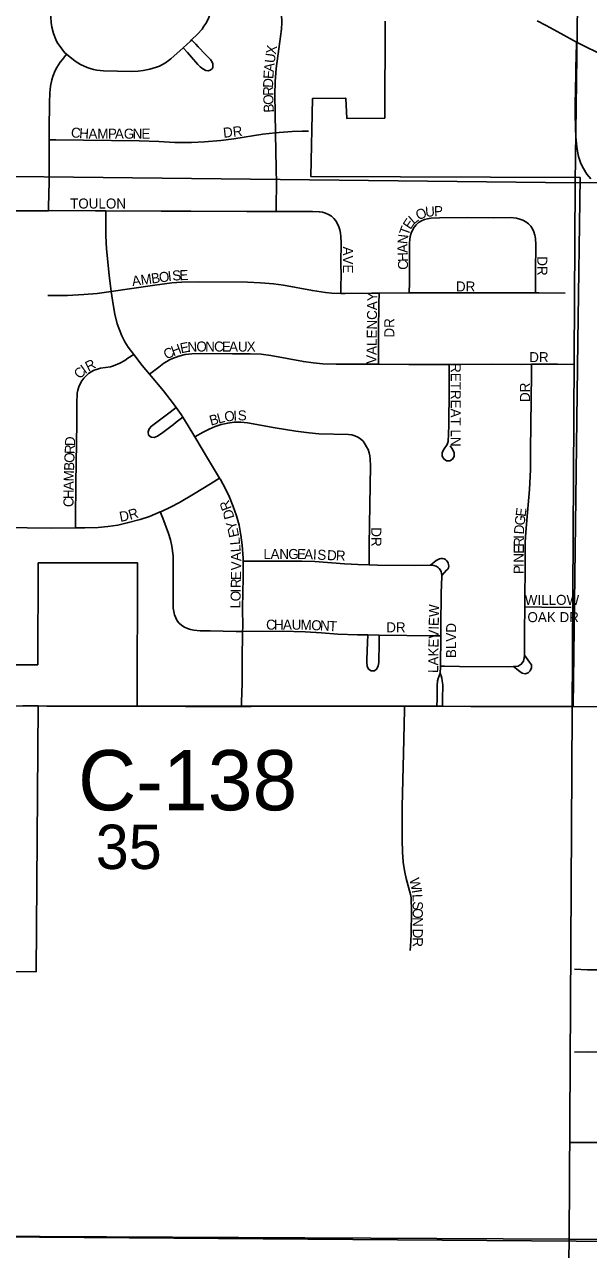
# Model space of a CAD drawing. Extents: x -97 to 34, y -21 to 22.
# Drawn here: x 7.079 to 7.611, y 17.448 to 18.604 of the extents above; entities that cross this region are included whole.
import ezdxf

# ---------------------------------------------------------------- set-up
doc = ezdxf.new("R2010")
doc.units = 0
for name, color, linetype in [('GM_X_City_Street', 7, 'Continuous'), ('GM_X_City_Street_Text', 7, 'Continuous'), ('GM_X_Corporation', 7, 'Continuous'), ('GM_X_County_Road', 7, 'Continuous'), ('GM_X_County_Road_Text', 7, 'Continuous'), ('GM_X_Section', 7, 'Continuous'), ('GM_X_Section_Text', 7, 'Continuous'), ('GM_X_State_Route', 7, 'Continuous'), ('GM_X_Township', 7, 'Continuous'), ('GM_X_Township_Subdivision', 7, 'Continuous'), ('GM_X_Township_Subdivision_Text', 7, 'Continuous')]:
    doc.layers.add(name, color=color, linetype=linetype)

msp = doc.modelspace()

# ---------------------------------------------------------------- linework, layer by layer
at = {"layer": 'GM_X_City_Street'}
for points in [[(7.3157, 18.5021), (7.315, 18.5384), (7.3153, 18.5507), (7.3163, 18.563), (7.3187, 18.5815), (7.3208, 18.5954), (7.3211, 18.5978), (7.3213, 18.5999), (7.3215, 18.6062), (7.321, 18.6217), (7.3209, 18.6341), (7.3203, 18.6589), (7.3198, 18.6775), (7.3192, 18.6838), (7.3186, 18.6869), (7.3178, 18.69), (7.3169, 18.6923)], [(7.2364, 18.5898), (7.2421, 18.5953), (7.2463, 18.6001), (7.2481, 18.6027), (7.2498, 18.6054), (7.2514, 18.6082), (7.2527, 18.611), (7.2549, 18.617), (7.2557, 18.6201), (7.2563, 18.6232), (7.2566, 18.6264), (7.2569, 18.6327), (7.2566, 18.6359), (7.2561, 18.639), (7.2513, 18.6635), (7.2497, 18.6712)], [(7.1185, 18.5764), (7.1166, 18.5781), (7.1139, 18.5813), (7.1097, 18.5874), (7.1083, 18.5902), (7.1062, 18.596), (7.1046, 18.602), (7.1039, 18.6062), (7.1036, 18.6113), (7.1035, 18.633), (7.1039, 18.6507)], [(7.1185, 18.5764), (7.1266, 18.5697), (7.1317, 18.5665), (7.1378, 18.5637), (7.1408, 18.5627), (7.1439, 18.5619), (7.147, 18.5613), (7.1533, 18.5607), (7.1798, 18.5601), (7.1861, 18.5604), (7.1909, 18.561), (7.1971, 18.5622), (7.2032, 18.564), (7.2061, 18.5652), (7.209, 18.5666), (7.2117, 18.5682), (7.2144, 18.5701), (7.2168, 18.5721), (7.2284, 18.5825)], [(7.2284, 18.5825), (7.2327, 18.5778), (7.2365, 18.5736), (7.2424, 18.5667), (7.2446, 18.5645), (7.247, 18.5626), (7.2498, 18.5611), (7.252, 18.5607), (7.254, 18.5612), (7.2558, 18.5624), (7.2565, 18.5638), (7.2566, 18.5656), (7.2564, 18.5672), (7.2559, 18.5688), (7.2542, 18.5713), (7.2497, 18.5762), (7.2428, 18.5833), (7.2405, 18.5857), (7.2364, 18.5898)], [(7.2284, 18.5825), (7.2353, 18.5888), (7.2364, 18.5898)], [(7.1021, 18.4955), (7.1021, 18.5057), (7.1024, 18.5306), (7.1027, 18.5399), (7.1033, 18.5461), (7.1045, 18.5522), (7.1054, 18.5552), (7.1077, 18.561), (7.1091, 18.5638), (7.1107, 18.5664), (7.1125, 18.5689), (7.1145, 18.5713), (7.1185, 18.5764)], [(7.1021, 18.4955), (7.1083, 18.4954), (7.1343, 18.4951), (7.1869, 18.4947), (7.2054, 18.4938), (7.2208, 18.493), (7.2363, 18.493), (7.2486, 18.4935), (7.264, 18.4948), (7.2763, 18.4964), (7.3037, 18.5008), (7.3157, 18.5021)], [(7.3157, 18.5021), (7.3191, 18.5025), (7.3314, 18.5035), (7.3407, 18.5037), (7.3469, 18.5036)], [(7.3163, 18.4278), (7.3163, 18.433), (7.3165, 18.4544), (7.3163, 18.4687), (7.3157, 18.5012), (7.3157, 18.5021)], [(7.1015, 18.4286), (7.1015, 18.4324), (7.102, 18.4559), (7.1021, 18.4777), (7.1021, 18.4955)], [(7.0331, 18.4288), (7.0556, 18.4286), (7.0649, 18.4285), (7.0866, 18.4285), (7.1015, 18.4286)], [(7.1015, 18.4286), (7.1053, 18.4287), (7.1456, 18.4286), (7.1554, 18.4285)], [(7.1607, 18.3525), (7.1587, 18.3677), (7.1562, 18.3925), (7.1555, 18.4048), (7.1554, 18.4243), (7.1554, 18.4285)], [(7.1554, 18.4285), (7.2078, 18.4283), (7.2357, 18.4281), (7.2885, 18.428), (7.3163, 18.4278)], [(7.3163, 18.4278), (7.3196, 18.4278), (7.3507, 18.428), (7.3569, 18.4276), (7.3599, 18.4271), (7.3629, 18.4263), (7.3658, 18.4251), (7.3685, 18.4235), (7.3708, 18.4214), (7.3726, 18.419), (7.3742, 18.4163), (7.3755, 18.4134), (7.3764, 18.4105), (7.3771, 18.4074), (7.3775, 18.4044), (7.3776, 18.3982), (7.3775, 18.3795), (7.3777, 18.3671), (7.3774, 18.3578), (7.3773, 18.3506)], [(7.4419, 18.351), (7.4421, 18.3609), (7.4423, 18.3702), (7.4422, 18.3982), (7.4424, 18.4014), (7.4429, 18.4044), (7.4437, 18.4074), (7.4449, 18.4103), (7.4465, 18.413), (7.4485, 18.4154), (7.4508, 18.4175), (7.4534, 18.4192), (7.4563, 18.4204), (7.4593, 18.4211), (7.4624, 18.4216), (7.4705, 18.4218), (7.4966, 18.4221), (7.5216, 18.422), (7.5371, 18.4221), (7.5403, 18.4219), (7.5433, 18.4215), (7.5464, 18.4208), (7.5493, 18.4197), (7.552, 18.4182), (7.5545, 18.4163), (7.5566, 18.414), (7.5583, 18.4114), (7.5596, 18.4086), (7.5605, 18.4056), (7.561, 18.4025), (7.5613, 18.3963), (7.5612, 18.3714), (7.5612, 18.3589), (7.5612, 18.351)], [(7.1607, 18.3525), (7.1995, 18.358), (7.2179, 18.3605), (7.2272, 18.3611), (7.2427, 18.3614), (7.2892, 18.3612), (7.3016, 18.3607), (7.3139, 18.3595), (7.3231, 18.3582), (7.3506, 18.3533), (7.3629, 18.3513), (7.369, 18.3508), (7.3773, 18.3506)], [(7.1008, 18.3485), (7.1039, 18.3485), (7.1194, 18.3487), (7.1349, 18.3494), (7.1473, 18.3505), (7.1607, 18.3525)], [(7.1818, 18.2928), (7.1767, 18.2997), (7.1736, 18.305), (7.1707, 18.3105), (7.1683, 18.3161), (7.1663, 18.3219), (7.164, 18.3309), (7.1623, 18.34), (7.1607, 18.3525)], [(7.3773, 18.3506), (7.3814, 18.3505), (7.4062, 18.3509), (7.4134, 18.3509)], [(7.413, 18.2838), (7.4129, 18.2894), (7.4128, 18.315), (7.4132, 18.3406), (7.4134, 18.3509)], [(7.4134, 18.3509), (7.4419, 18.351)], [(7.4419, 18.351), (7.49, 18.351), (7.5612, 18.351)], [(7.5612, 18.351), (7.5644, 18.351), (7.5892, 18.3509)], [(7.1268, 18.1292), (7.1268, 18.1373), (7.1272, 18.1717), (7.1281, 18.2281), (7.1281, 18.2501), (7.1283, 18.2532), (7.1286, 18.2563), (7.1292, 18.2594), (7.1301, 18.2624), (7.1313, 18.2653), (7.1329, 18.268), (7.1347, 18.2705), (7.1369, 18.2728), (7.1392, 18.2749), (7.1418, 18.2766), (7.1446, 18.278), (7.1475, 18.2791), (7.1506, 18.2799), (7.1599, 18.2814), (7.1629, 18.2823), (7.1687, 18.2846), (7.1733, 18.2873), (7.1763, 18.2893), (7.1818, 18.2928)], [(7.1967, 18.2743), (7.1898, 18.2825), (7.1818, 18.2928)], [(7.1967, 18.2743), (7.2054, 18.2809), (7.2104, 18.2846), (7.213, 18.2863), (7.2157, 18.2878), (7.2186, 18.2892), (7.2244, 18.2913), (7.2305, 18.2928), (7.2366, 18.2937), (7.2451, 18.2939), (7.2751, 18.2937), (7.2918, 18.2935), (7.3021, 18.2932), (7.3113, 18.2919), (7.342, 18.2863), (7.3512, 18.2849), (7.3605, 18.2841), (7.373, 18.2837), (7.4104, 18.2838), (7.413, 18.2838)], [(7.413, 18.2838), (7.4416, 18.2834), (7.4795, 18.2836)], [(7.4806, 18.2067), (7.4827, 18.2036), (7.4842, 18.2), (7.4842, 18.1968), (7.4838, 18.1956), (7.4828, 18.1942), (7.4802, 18.1926), (7.4772, 18.1927), (7.4746, 18.1944), (7.4731, 18.197), (7.4731, 18.2), (7.4744, 18.2028), (7.4777, 18.208), (7.4787, 18.2109), (7.4791, 18.2177), (7.4792, 18.2262), (7.4795, 18.26), (7.4795, 18.2754), (7.4795, 18.2836)], [(7.4795, 18.2836), (7.5195, 18.2839), (7.5476, 18.2836), (7.5573, 18.2837)], [(7.551, 18.0548), (7.5511, 18.0726), (7.5514, 18.0816), (7.5515, 18.0941), (7.5515, 18.1159), (7.5519, 18.1252), (7.5535, 18.1438), (7.5555, 18.1655), (7.5564, 18.1842), (7.5564, 18.2029), (7.5572, 18.2745), (7.5573, 18.2837)], [(7.5573, 18.2837), (7.5819, 18.2837), (7.5975, 18.2835)], [(7.2219, 18.2428), (7.2194, 18.2463), (7.2098, 18.2587), (7.1967, 18.2743)], [(7.2281, 18.2338), (7.2219, 18.229), (7.2195, 18.227), (7.2094, 18.2194), (7.2042, 18.2157), (7.2012, 18.2146), (7.1982, 18.2149), (7.1959, 18.2169), (7.1954, 18.22), (7.1964, 18.2229), (7.1986, 18.2252), (7.2162, 18.2386), (7.2219, 18.2428)], [(7.2281, 18.2338), (7.2266, 18.2362), (7.2219, 18.2428)], [(7.2394, 18.2153), (7.2333, 18.2256), (7.2281, 18.2338)], [(7.2394, 18.2153), (7.2474, 18.2195), (7.2529, 18.2224), (7.2586, 18.2249), (7.2645, 18.2268), (7.2706, 18.2282), (7.2767, 18.2289), (7.2829, 18.2289), (7.2891, 18.2284), (7.3154, 18.2236), (7.335, 18.2204), (7.3473, 18.2189), (7.3566, 18.2181), (7.3845, 18.2174), (7.3876, 18.217), (7.3905, 18.216), (7.3934, 18.2148), (7.396, 18.2132), (7.3983, 18.2111), (7.4001, 18.2086), (7.4017, 18.2059), (7.403, 18.2031), (7.404, 18.2002), (7.4047, 18.1972), (7.4051, 18.1941), (7.4052, 18.1879), (7.4046, 18.1506), (7.4042, 18.1134), (7.4042, 18.0978), (7.4041, 18.0944)], [(7.2629, 18.1762), (7.2523, 18.1936), (7.2394, 18.2153)], [(7.2069, 18.1443), (7.2082, 18.1448), (7.2166, 18.1488), (7.2249, 18.1531), (7.2382, 18.1611), (7.2542, 18.1708), (7.2629, 18.1762)], [(7.2851, 18.0979), (7.2851, 18.1006), (7.2842, 18.1131), (7.2831, 18.1224), (7.2813, 18.1317), (7.2788, 18.1407), (7.2758, 18.1496), (7.2723, 18.1583), (7.2682, 18.1668), (7.2637, 18.175), (7.2629, 18.1762)], [(7.1268, 18.1292), (7.1357, 18.1293), (7.1482, 18.1297), (7.1575, 18.1305), (7.1667, 18.1319), (7.1758, 18.1339), (7.1878, 18.1371), (7.1967, 18.1401), (7.2069, 18.1443)], [(7.2069, 18.1443), (7.2092, 18.1383), (7.2148, 18.124), (7.2166, 18.1181), (7.2179, 18.112), (7.219, 18.1028), (7.2192, 18.096), (7.2191, 18.0874), (7.219, 18.0565), (7.2191, 18.0534), (7.2196, 18.0503), (7.2204, 18.0473), (7.2215, 18.0444), (7.2229, 18.0417), (7.2247, 18.0392), (7.2271, 18.0372), (7.2297, 18.0355), (7.2325, 18.0343), (7.2355, 18.0334), (7.2385, 18.0328), (7.2447, 18.0321), (7.2539, 18.032), (7.2787, 18.0315), (7.2846, 18.0315)], [(6.8463, 18.1312), (6.8681, 18.1308), (6.9086, 18.1304), (6.9615, 18.1301), (7.0268, 18.1297), (7.058, 18.1296), (7.1046, 18.1291), (7.1268, 18.1292)], [(7.2846, 18.0315), (7.2847, 18.0353), (7.2846, 18.054), (7.2851, 18.0819), (7.2851, 18.0979)], [(7.2851, 18.0979), (7.2936, 18.0979), (7.3404, 18.098), (7.3529, 18.0976), (7.3809, 18.0953), (7.3934, 18.0946), (7.4041, 18.0944)], [(7.4041, 18.0944), (7.4121, 18.0942), (7.4465, 18.0939), (7.4621, 18.0941)], [(7.4726, 18.0844), (7.4772, 18.0893), (7.4782, 18.0903), (7.4789, 18.0916), (7.4792, 18.0931), (7.4791, 18.0945), (7.4787, 18.0962), (7.4781, 18.0973), (7.4772, 18.0986), (7.4761, 18.0995), (7.4748, 18.1), (7.4733, 18.1004), (7.4718, 18.1005), (7.4704, 18.1002), (7.4674, 18.0984), (7.4621, 18.0941)], [(7.4726, 18.0844), (7.4724, 18.0864), (7.4721, 18.0878), (7.4714, 18.0894), (7.4703, 18.0908), (7.4691, 18.092), (7.4672, 18.0932), (7.4652, 18.0938), (7.4621, 18.0941)], [(7.4716, 18.0274), (7.4716, 18.036), (7.4721, 18.0676), (7.4727, 18.0833), (7.4726, 18.0844)], [(7.5507, 18.0092), (7.5508, 18.0098), (7.5507, 18.0315), (7.551, 18.0548)], [(7.551, 18.0548), (7.5671, 18.0546), (7.5948, 18.0541)], [(7.2835, 17.9607), (7.2836, 17.965), (7.2841, 17.9824), (7.2842, 18.0042), (7.2846, 18.0315)], [(7.2846, 18.0315), (7.322, 18.0317), (7.3437, 18.0313), (7.3591, 18.0303), (7.3746, 18.029), (7.3931, 18.0283), (7.4027, 18.0282)], [(7.4027, 18.0282), (7.4024, 18.021), (7.4018, 18.0052), (7.4018, 18.0021), (7.4023, 17.9989), (7.4036, 17.996), (7.406, 17.9943), (7.409, 17.9943), (7.4114, 17.9961), (7.4127, 17.999), (7.4131, 18.0021), (7.4135, 18.0211), (7.4136, 18.028)], [(7.4027, 18.0282), (7.4136, 18.028)], [(7.4136, 18.028), (7.4396, 18.0278), (7.4612, 18.0274), (7.4643, 18.0274), (7.4716, 18.0274)], [(7.4714, 17.9988), (7.4716, 18.0274)], [(7.5405, 17.9983), (7.5415, 17.9984), (7.5447, 17.9989), (7.5477, 18.0006), (7.5497, 18.0035), (7.5505, 18.0066), (7.5507, 18.0092)], [(7.5405, 17.9983), (7.5462, 17.9938), (7.5485, 17.992), (7.5514, 17.9915), (7.5541, 17.9925), (7.5562, 17.9945), (7.5573, 17.9972), (7.5572, 18.0001), (7.5555, 18.0024), (7.5507, 18.0092)], [(7.4681, 17.9609), (7.4682, 17.9677), (7.4682, 17.9801), (7.4687, 17.9848), (7.4692, 17.9871), (7.4701, 17.9897), (7.4712, 17.992)], [(7.4712, 17.992), (7.4714, 17.9982), (7.4714, 17.9988)], [(7.4734, 17.9609), (7.4734, 17.9673), (7.4735, 17.981), (7.4731, 17.9848), (7.4726, 17.9873), (7.4721, 17.9896), (7.4712, 17.992)], [(7.4714, 17.9988), (7.4751, 17.9987), (7.4895, 17.9985), (7.5352, 17.9982), (7.5405, 17.9983)]]:
    msp.add_lwpolyline(points, dxfattribs=at)
at = {"layer": 'GM_X_Corporation'}
for points in [[(7.0457, 18.0001), (7.0912, 18.0001), (7.0917, 18.0962), (7.1854, 18.0963), (7.185, 17.9609), (7.4374, 17.961), (7.5966, 17.9608), (7.601, 18.3052), (7.6032, 18.46), (7.349, 18.461), (7.3506, 18.5345), (7.3822, 18.5348), (7.383, 18.5157), (7.4188, 18.516), (7.4193, 18.6075)], [(6.8341, 17.7116), (7.0896, 17.7104), (7.0916, 17.9612), (7.0465, 17.961)]]:
    msp.add_lwpolyline(points, dxfattribs=at)
at = {"layer": 'GM_X_County_Road'}
for points in [[(7.5999, 18.5877), (7.6279, 18.5738), (7.6692, 18.5522), (7.7268, 18.5216), (7.7791, 18.4942), (7.8205, 18.4728), (7.8317, 18.4674), (7.8403, 18.4637), (7.8492, 18.4606), (7.8552, 18.4589), (7.8644, 18.457), (7.8737, 18.456), (7.8862, 18.4555), (7.9266, 18.4551), (7.9614, 18.4546)], [(7.0465, 17.961), (7.0592, 17.961), (7.0682, 17.9611), (7.0772, 17.9613), (7.0822, 17.9612), (7.0916, 17.9612)], [(7.0916, 17.9612), (7.0997, 17.961), (7.118, 17.961), (7.185, 17.9609)], [(7.185, 17.9609), (7.2057, 17.961), (7.2306, 17.9607), (7.2835, 17.9607)], [(7.2835, 17.9607), (7.2928, 17.9607), (7.3653, 17.9609), (7.4374, 17.961)], [(7.4374, 17.961), (7.4422, 17.961), (7.4681, 17.9609)], [(7.4681, 17.9609), (7.4734, 17.9609)], [(7.4734, 17.9609), (7.5, 17.9608), (7.5555, 17.9608), (7.5853, 17.9608), (7.5966, 17.9608)], [(7.5966, 17.9608), (7.684, 17.9602), (7.7042, 17.9602)]]:
    msp.add_lwpolyline(points, dxfattribs=at)
at = {"layer": 'GM_X_Section'}
for points in [[(8.6298, 19.4815), (8.6297, 19.4743), (8.6166, 18.456), (7.5986, 18.4548), (7.611, 19.4121)], [(6.6081, 19.4622), (7.611, 19.4121), (7.5986, 18.4548), (6.5955, 18.4662)], [(6.5955, 18.4662), (7.5986, 18.4548), (7.5928, 17.458), (6.5942, 17.463)], [(7.5986, 18.4548), (8.6166, 18.456), (8.6036, 17.4499), (7.5928, 17.458)], [(7.5928, 17.458), (7.5768, 16.4545), (6.5713, 16.4562), (6.5942, 17.463)], [(8.6036, 17.4499), (8.5841, 16.4464), (7.5768, 16.4545), (7.5928, 17.458)]]:
    msp.add_lwpolyline(points, close=True, dxfattribs=at)
at = {"layer": 'GM_X_State_Route'}
msp.add_lwpolyline([(7.5627, 18.6078), (7.5713, 18.6033), (7.5851, 18.596), (7.5999, 18.5877), (7.5997, 18.5827), (7.5996, 18.5787), (7.5989, 18.5408), (7.5987, 18.5313), (7.5987, 18.529), (7.5986, 18.5197), (7.5988, 18.5073), (7.5992, 18.4981), (7.6, 18.4889), (7.601, 18.4828), (7.6017, 18.4799), (7.6025, 18.4769), (7.6036, 18.4741), (7.6049, 18.4713), (7.6063, 18.4686), (7.6097, 18.4632), (7.6135, 18.4588)], dxfattribs=at)
at = {"layer": 'GM_X_Township'}
msp.add_lwpolyline([(3.5515, 17.4809), (4.0699, 17.4738), (4.7305, 17.4694), (4.9411, 17.4679), (5.2744, 17.4682), (6.3326, 17.4656), (8.1906, 17.4518), (8.5806, 17.4486), (8.6046, 17.4491), (8.6147, 18.2447), (8.6237, 19.1499), (8.6285, 19.5942), (8.6399, 20.3469), (8.639, 20.4457), (8.6444, 20.7413), (8.6434, 20.7554), (8.6417, 20.8163), (8.6417, 20.8177)], dxfattribs=at)
at = {"layer": 'GM_X_Township_Subdivision'}
for points in [[(7.4361, 17.8143), (7.4355, 17.8228), (7.4354, 17.8353), (7.4354, 17.8664), (7.4365, 17.9163), (7.4373, 17.9575), (7.4374, 17.961)], [(7.4428, 17.7303), (7.443, 17.7346), (7.4434, 17.7396), (7.4436, 17.7459), (7.4439, 17.7677), (7.4436, 17.7801), (7.4432, 17.7832), (7.4391, 17.7982), (7.4378, 17.8043), (7.4362, 17.8135), (7.4361, 17.8143)], [(7.5979, 17.7127), (7.6103, 17.7123), (7.6413, 17.7121), (7.666, 17.712), (7.7183, 17.7112), (7.7207, 17.7112)], [(7.5979, 17.6345), (7.6103, 17.6346), (7.6319, 17.6344), (7.6659, 17.6343), (7.7029, 17.634), (7.7193, 17.6339)], [(7.5942, 17.5493), (7.6046, 17.5492), (7.6264, 17.5491), (7.6375, 17.549), (7.6554, 17.5489), (7.6746, 17.5487), (7.6897, 17.5486), (7.7175, 17.5485), (7.7179, 17.5485)]]:
    msp.add_lwpolyline(points, dxfattribs=at)

# ---------------------------------------------------------------- texts
at = {"layer": 'GM_X_City_Street_Text'}
for s, rotation, p in [('X', 81.1558, (7.3159, 18.5757)), ('U', 82.3707, (7.3148, 18.5675)), ('E', 86.2822, (7.3136, 18.5527)), ('A', 84.1328, (7.314, 18.5593)), ('D', 88.7323, (7.3134, 18.5445)), ('R', 90.7043, (7.3135, 18.5371)), ('O', 92.6878, (7.3139, 18.5288)), ('B', 92.672, (7.3142, 18.5214)), ('C', 352.5979, (7.1221, 18.4982)), ('H', 355.9615, (7.1301, 18.4972)), ('A', 359.9253, (7.1391, 18.4966)), ('M', 0.0001, (7.1475, 18.4966)), ('P', 0, (7.1575, 18.4966)), ('A', 0, (7.1641, 18.4966)), ('G', 0, (7.1725, 18.4966)), ('N', 0, (7.1808, 18.4966)), ('E', 0, (7.1891, 18.4966)), ('DR', 6.0024, (7.2667, 18.4974)), ('TOULON', 0, (7.1218, 18.4307)), ('O', 26.3402, (7.4508, 18.4193)), ('U', 4.1791, (7.4573, 18.4228)), ('P', 2.1312, (7.4655, 18.4234)), ('E', 56.7722, (7.4431, 18.4103)), ('L', 40.4946, (7.4462, 18.4153)), ('T', 69.5079, (7.441, 18.4045)), ('A', 91.6834, (7.4404, 18.3889)), ('N', 83.3846, (7.4401, 18.3968)), ('AVE', 270, (7.3794, 18.3948)), ('H', 91.6834, (7.4407, 18.3805)), ('DR', 270, (7.5628, 18.3856)), ('S', 5.0336, (7.2186, 18.3625)), ('E', 1.6397, (7.2251, 18.363)), ('C', 91.6761, (7.4409, 18.373)), ('A', 7.716, (7.1807, 18.3574)), ('M', 7.7102, (7.189, 18.3585)), ('B', 7.7017, (7.1989, 18.3598)), ('O', 7.6943, (7.2063, 18.3608)), ('I', 6.881, (7.2146, 18.362)), ('DR', 0, (7.486, 18.3524)), ('VALENCAY', 89.2429, (7.4109, 18.284)), ('DR', 90, (7.4278, 18.3089)), ('H', 20.3846, (7.2192, 18.2912)), ('E', 11.3582, (7.2266, 18.294)), ('N', 3.1495, (7.2328, 18.2952)), ('O', 0.2842, (7.241, 18.2957)), ('N', 0, (7.2493, 18.2957)), ('C', 0, (7.2577, 18.2957)), ('E', 0, (7.2652, 18.2957)), ('A', 0, (7.2718, 18.2957)), ('U', 0, (7.2802, 18.2957)), ('X', 0, (7.2885, 18.2957)), ('C', 25.5657, (7.2127, 18.288)), ('DR', 0, (7.5552, 18.2857)), ('C', 47.3359, (7.1312, 18.2692)), ('I', 35.7766, (7.1359, 18.2743)), ('R', 26.8366, (7.139, 18.2766)), ('RETREAT LN', 270, (7.4811, 18.2848)), ('DR', 90, (7.5559, 18.2481)), ('B', 15.1848, (7.2547, 18.2257)), ('L', 15.1925, (7.2619, 18.2276)), ('O', 8.5783, (7.2681, 18.2293)), ('I', 2.0111, (7.276, 18.2305)), ('S', 0.4372, (7.2801, 18.2307)), ('D', 87.8874, (7.1263, 18.2063)), ('O', 87.8797, (7.1257, 18.1905)), ('R', 87.8627, (7.1261, 18.1988)), ('B', 87.887, (7.1255, 18.183)), ('M', 88.0508, (7.1251, 18.173)), ('A', 89.4316, (7.125, 18.1648)), ('H', 89.9812, (7.125, 18.1564)), ('C', 89.9757, (7.125, 18.1489)), ('R', 110.4128, (7.2745, 18.1477)), ('D', 10.5297, (7.1692, 18.1349)), ('R', 16.3696, (7.1784, 18.1367)), ('D', 105.6902, (7.277, 18.1389)), ('G', 83.2518, (7.5507, 18.1311)), ('E', 83.1257, (7.5517, 18.1394)), ('Y', 105.4935, (7.28, 18.1284)), ('E', 102.3526, (7.2815, 18.1214)), ('D', 85.6901, (7.5501, 18.1229)), ('L', 95.6078, (7.2824, 18.1135)), ('DR', 270, (7.4061, 18.1298)), ('I', 89.6067, (7.5501, 18.1189)), ('R', 89.9514, (7.5501, 18.1114)), ('L', 94.4688, (7.2829, 18.1067)), ('A', 92.4615, (7.2833, 18.098)), ('L', 359.9727, (7.3043, 18.0999)), ('A', 359.9929, (7.311, 18.0999)), ('N', 359.9781, (7.3193, 18.0999)), ('G', 359.9781, (7.3277, 18.0999)), ('E', 359.0438, (7.3359, 18.0999)), ('A', 357.8142, (7.3426, 18.0998)), ('I', 357.6832, (7.3509, 18.0995)), ('S', 357.6493, (7.355, 18.0993)), ('D', 357.6605, (7.3642, 18.0989)), ('R', 357.6652, (7.3725, 18.0986)), ('E', 89.9572, (7.5501, 18.1048)), ('V', 89.1144, (7.2832, 18.0891)), ('N', 89.9563, (7.55, 18.0964)), ('I', 89.9573, (7.55, 18.0923)), ('E', 89.0165, (7.283, 18.0799)), ('P', 89.9453, (7.55, 18.0856)), ('R', 89.0286, (7.2829, 18.0724)), ('O', 89.0355, (7.2827, 18.0599)), ('L', 89.0165, (7.2825, 18.0532)), ('I', 89.058, (7.2828, 18.0682)), ('WILLOW', 0, (7.551, 18.0566)), ('LAKEVIEW', 89.2143, (7.4692, 17.9923)), ('OAK DR', 0, (7.5535, 18.0403)), ('C', 359.9757, (7.3068, 18.0332)), ('H', 359.9703, (7.3143, 18.0332)), ('A', 359.9703, (7.3227, 18.0332)), ('U', 359.9703, (7.331, 18.0332)), ('M', 358.2511, (7.3392, 18.0332)), ('O', 356.9608, (7.3492, 18.0329)), ('N', 356.9171, (7.3575, 18.0325)), ('T', 356.9111, (7.3658, 18.032)), ('DR', 0, (7.4202, 18.0307)), ('BLVD', 90, (7.4862, 18.0064))]:
    msp.add_text(s, height=0.00947, rotation=rotation, dxfattribs=at).set_placement(p)
at = {"layer": 'GM_X_County_Road_Text'}
msp.add_text('C-138', height=0.05682, rotation=0, dxfattribs=at).set_placement((7.1293, 17.8627))
at = {"layer": 'GM_X_Section_Text'}
msp.add_text('35', height=0.04186, rotation=0, dxfattribs=at).set_placement((7.146, 17.8073))
at = {"layer": 'GM_X_Township_Subdivision_Text'}
for s, rotation, p in [('W', 282.9883, (7.4419, 17.7977)), ('I', 279.4408, (7.4443, 17.7873)), ('L', 272.6782, (7.4449, 17.7835)), ('S', 270.1639, (7.4453, 17.7769)), ('O', 270, (7.4453, 17.7703)), ('N', 269.9928, (7.4453, 17.7619)), ('D', 269.9928, (7.4453, 17.7511)), ('R', 269.994, (7.4453, 17.7428))]:
    msp.add_text(s, height=0.00947, rotation=rotation, dxfattribs=at).set_placement(p)

doc.saveas('drawing.dxf')
